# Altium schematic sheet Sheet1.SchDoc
size B
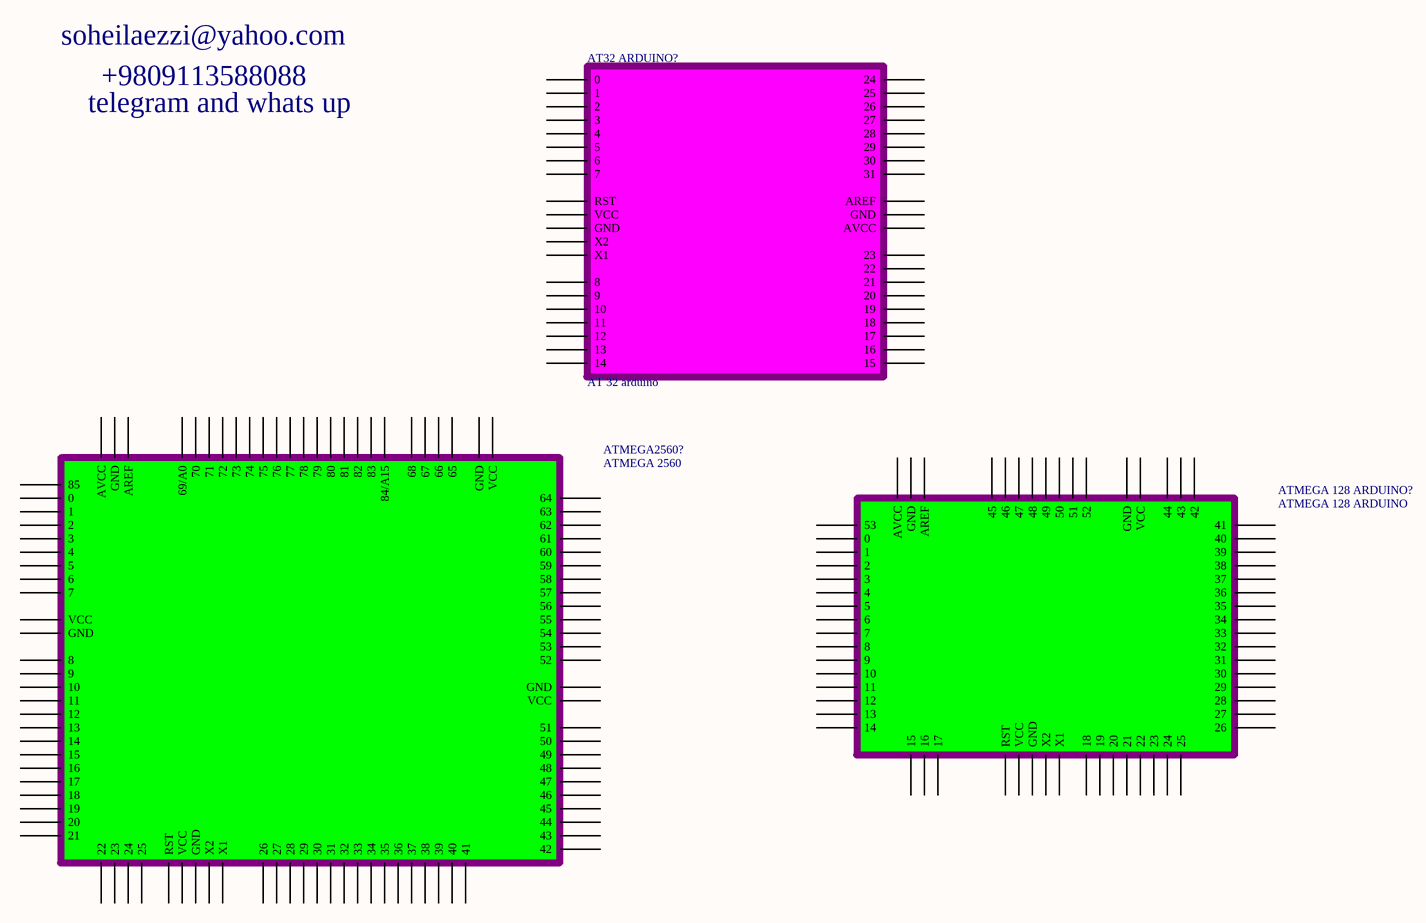
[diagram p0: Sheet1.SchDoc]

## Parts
AT32_ARDUINO?  AT 32 arduino  [Dip40]
ATMEGA2560?  ATMEGA 2560  [ATMEGA 2560]
ATMEGA_128_ARDUINO?  ATMEGA 128 ARDUINO  [ATMEGA 128 64 ARDUINO]

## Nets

Not connected (* = marked no-connect by the designer): AT32_ARDUINO? 0 1 2 3 4 5 6 7 8 9 10 11 12 13 14 15 16 17 18 19 20 21 22 23 24 25 26 27 28 29 30 31 AREF AVCC GND RST VCC X1 X2; ATMEGA2560? 0 1 2 3 4 5 6 7 8 9 10 11 12 13 14 15 16 17 18 19 20 21 22 23 24 25 26 27 28 29 30 31 32 33 34 35 36 37 38 39 40 41 42 43 44 45 46 47 48 49 50 51 52 53 54 55 56 57 58 59 60 61 62 63 64 65 66 67 68 69(69/A0) 70 71 72 73 74 75 76 77 78 79 80 81 82 83 84(84/A15) 85 AREF AVCC GND RST VCC; ATMEGA_128_ARDUINO? 0 1 2 3 4 5 6 7 8 9 10 11 12 13 14 15 16 17 18 19 20 21 22 23 24 25 26 27 28 29 30 31 32 33 34 35 36 37 38 39 40 41 42 43 44 45 46 47 48 49 50 51 52 53 AREF AVCC GND RST VCC

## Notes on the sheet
- soheilaezzi@yahoo.com
- +9809113588088
- telegram and whats up

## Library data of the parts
AT32_ARDUINO? = ATMEGA 32 ARDUINO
